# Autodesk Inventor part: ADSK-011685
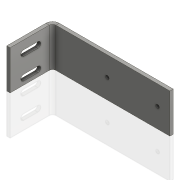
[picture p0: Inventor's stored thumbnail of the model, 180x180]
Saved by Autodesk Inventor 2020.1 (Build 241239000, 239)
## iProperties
Created: 2000-02
Part Number: ADSK-011685
Material: 1.0312 DC05
Document SubType Name: Tôlerie
Description: FSHTPH,FH,CP,02,085,032,030,090,MNT,BEARING
Designer: sspink
Density: 1 g/cm^3
Sheet Metal Rule: Stahlblech 1.0312 - DC05 -   6.0 mm
Appearance: Stahl
Mass: 116.453 g
Surface Area: 443.643 cm^2
Volume: 116.453 cm^3
Flat Pattern Width: 7 cm
Flat Pattern Length: 28.7572 cm
Flat Pattern Area: 201.3 cm^2
Sheet Metal Width: 70,000 mm
Sheet Metal Length: 287,572 mm
Sheet Metal Area: 20130,018 mm^2
Control State: 0
Checked Out: False
Master: False
Shininess: 25.0
Length Units: 11269
Angle Units: 11279
Time Units: 11290
Mass Units: 11283
Length Display Precision: 3
Angle Display Precision: 2
Compacted: True
Cutlength: 11.32
Material Desc: FLAT,HRS,0.25 X 3.00
Material_Number: A084336
G_L: 287,6x70 mm
Thickness: 6,000 mm
Dimensions: 216x70x82 mm
Mass: 0,116 kg
Semi finished: Stahlblech 1.0312 - DC05 -   6.0 mm
DocNumber: ADSK-011685.ipt
Folder: 01 - Themengebiete\Simplification\01 - Packaging machine\
VDS_Category: 3D Komponenten
Density: 0.0
Volumn: 0.0
Area: 0.0
PropertySet Name: Model Information
Author: sspink
Revision Number: -
Title: FSHTPH,FH,CP,02,085,032,030,090,MNT,BEARING
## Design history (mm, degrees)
workpoint "Arbeitspunkt1"
workpoint "Arbeitspunkt2"
workaxis "Arbeitsachse1"
workaxis "Arbeitsachse2"
pattern_linear "Rechteckige Anordnung2" dims "d47" = 38
sketch "Skizze5"
  geometry: L1 through (-35, 0) direction (1, 0); L2 through (0, 41) direction (0, 1); L3 (0, 82)-(-70, 82); L4 (-70, 82)-(-70, 0)
  constraints: 6 end point, 1 horizontal, 1 perpendicular, 1 vertical
feature "Grobblech3" dims "d28" = 6 (= Thickness), "d29" = 6 (= BendReliefWidth), "d30" = 3 (= BendReliefDepth), "d31" = 12 (= MinimumRemnant), "d32" = 6 (= TransitionRadius), "d33" = 82, "d34" = 90 deg, "d35" = 6 (= BendRadius), "d36" = 24 (= CornerReliefSize), "d37" = 6 (= TailleJeu), "d38" = 6 (= TailleRayonJacobi), "SeamGap" = 0.00508
feature "Biegung2" dims "d28" = 6 (= Thickness), "d29" = 6 (= BendReliefWidth), "d30" = 3 (= BendReliefDepth), "d31" = 12 (= MinimumRemnant), "d32" = 6 (= TransitionRadius), "d33" = 82, "d34" = 90 deg, "d35" = 6 (= BendRadius), "SeamGap" = 0.00508
node "Lasche2"
feature "Ecke1" dims "d33" = 82, "d34" = 90 deg, "d36" = 24 (= CornerReliefSize), "d37" = 6 (= TailleJeu), "d38" = 6 (= TailleRayonJacobi)
node "Solide1"
  node "Face1"
  node "Cut1" dims "d10" = 6 (= Thickness), "d11" = 0
  node "Hole1" dims "d19" = 6.647, "d20" = 9.525, "d21" = 6.35, "d22" = 60 deg, "d23" = 19.05, "d24" = 118 deg, "d44" = 16
sketch "Sketch1"
  geometry: L1 (-108, -35)-(108, -35); L2 (108, -35)-(108, 35); L3 (108, 35)-(-108, 35); L4 (-108, 35)-(-108, -35); 3 further points
  constraints: 8 end point, 2 midpoint, 2 parallel, 1 horizontal, 1 horizontal alignment, 1 perpendicular, 1 vertical alignment
  dimensions: "d0" = 216 distance between parallel lines of L2 L4; "d1" = 70 distance between parallel lines of L1 L3
node "Plate1" dims "d28" = 6 (= Thickness)
sketch "Sketch3"
  geometry: L1 (-24.85, -31.659)-(-50.25, -31.659); L2 (-50.25, -31.659)-(-50.25, -21.341); L3 (-50.25, -21.341)-(-24.85, -21.341); L4 (-24.85, -21.341)-(-24.85, -31.659); L5 (-24.85, -26.5)-(-50.25, -26.5); L6 (-70.55, -38)-(-0.55, -38) reference; L7 (-0.55, 32)-(-0.55, -38) reference; L8 (-70.55, -38)-(-70.55, 32) reference; L9 (-0.55, -3)-(-70.55, -3); A1 r 5.159 centre (-24.85, -26.5) between (-24.85, -31.659) and (-24.85, -21.341); A2 r 5.159 centre (-50.25, -26.5) between (-50.25, -21.341) and (-50.25, -31.659); 1 further point
  constraints: 12 end point, 4 point on circle, 3 midpoint, 2 centre point, 2 parallel, 2 perpendicular, 2 tangent, 1 horizontal
  dimensions: "d6" = 10.31875 distance between parallel lines of L3 L1; "d7" = 25.4 distance of L2.end L3.end; "d40" = 23.5 distance between parallel lines of L9 L5; "d41" = 37 distance from line of L7 point (-37.55, -26.5)
sketch "Sketch4"
  geometry: L1 (0, 70)-(0, 0) reference; 4 further points
  constraints: 3 horizontal alignment, 2 midpoint
  dimensions: "d42" = 90 distance of point (-22, 35) point (-112, 35); "d43" = 22 distance from line of L1 point (-22, 35)
node "FlatPattern"
node "Corps solides"
node "Corps surfaciques"
feature "Extrusion_mise_à_plat2" dims "d0" = 6 (derived)
other parameters: "Thickness" = 6 (derived), "BendRadius" = 6 (= Thickness), "BendReliefWidth" = 6 (= Thickness), "BendReliefDepth" = 3 (= 0.5 x Thickness), "CornerReliefSize" = 24 (= 4 x Thickness), "MinimumRemnant" = 12 (= 2 x Thickness), "d2" = 6 (= BendRadius), "d3" = 76.2, "d4" = 90 deg, "d5" = 6 (= BendRadius), "TransitionRadius" = 6 (= BendRadius), "TailleRayonJacobi" = 6 (= BendRadius), "TailleJeu" = 6 (= Thickness)
